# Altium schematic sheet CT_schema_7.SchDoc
size 147 x 119 mm
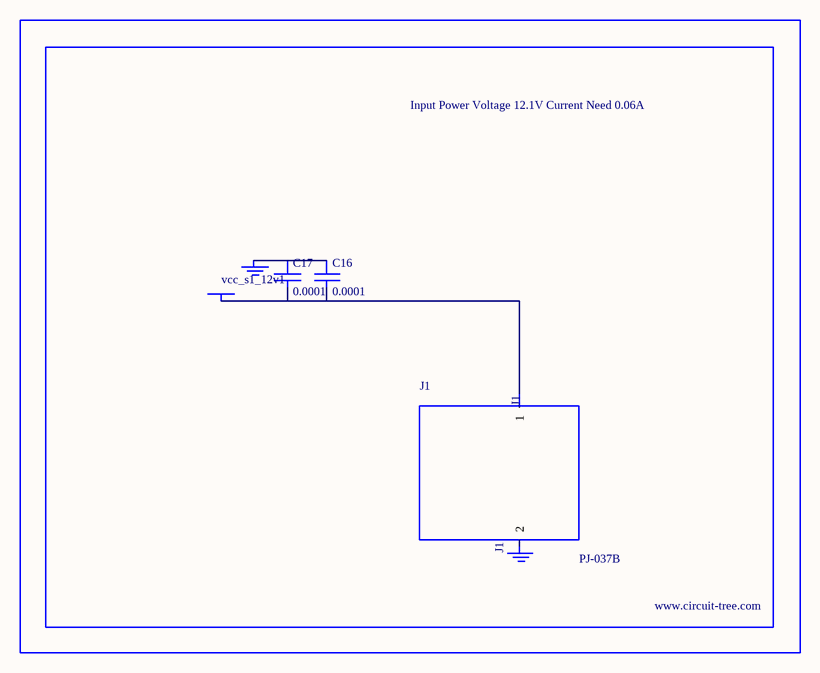
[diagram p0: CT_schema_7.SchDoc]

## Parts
BORDER6  (no value)
C16  0.0001  [EXV-9H]
C17  0.0001  [EXV-9H]
GND_INSTANCE_6_0  (no value)
GND_INSTANCE_6_1  (no value)
J1  PJ-037B  [PJ-037B_PACKAGE]
POWER_INSTANCE_6_0  vcc_s1_12v1

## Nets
NetC16_1: C16.1 C17.1 GND_INSTANCE_6_0.0(GND)
NetC16_2: C16.2 C17.2 J1.1 POWER_INSTANCE_6_0.0(PWR)

Not connected (* = marked no-connect by the designer): GND_INSTANCE_6_1 0(GND); J1 2

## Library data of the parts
BORDER6 = BORDER_PAGE6
C16 C17 = EDK107M035A9HAA
GND_INSTANCE_6_0 GND_INSTANCE_6_1 = GND
POWER_INSTANCE_6_0 = PWR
